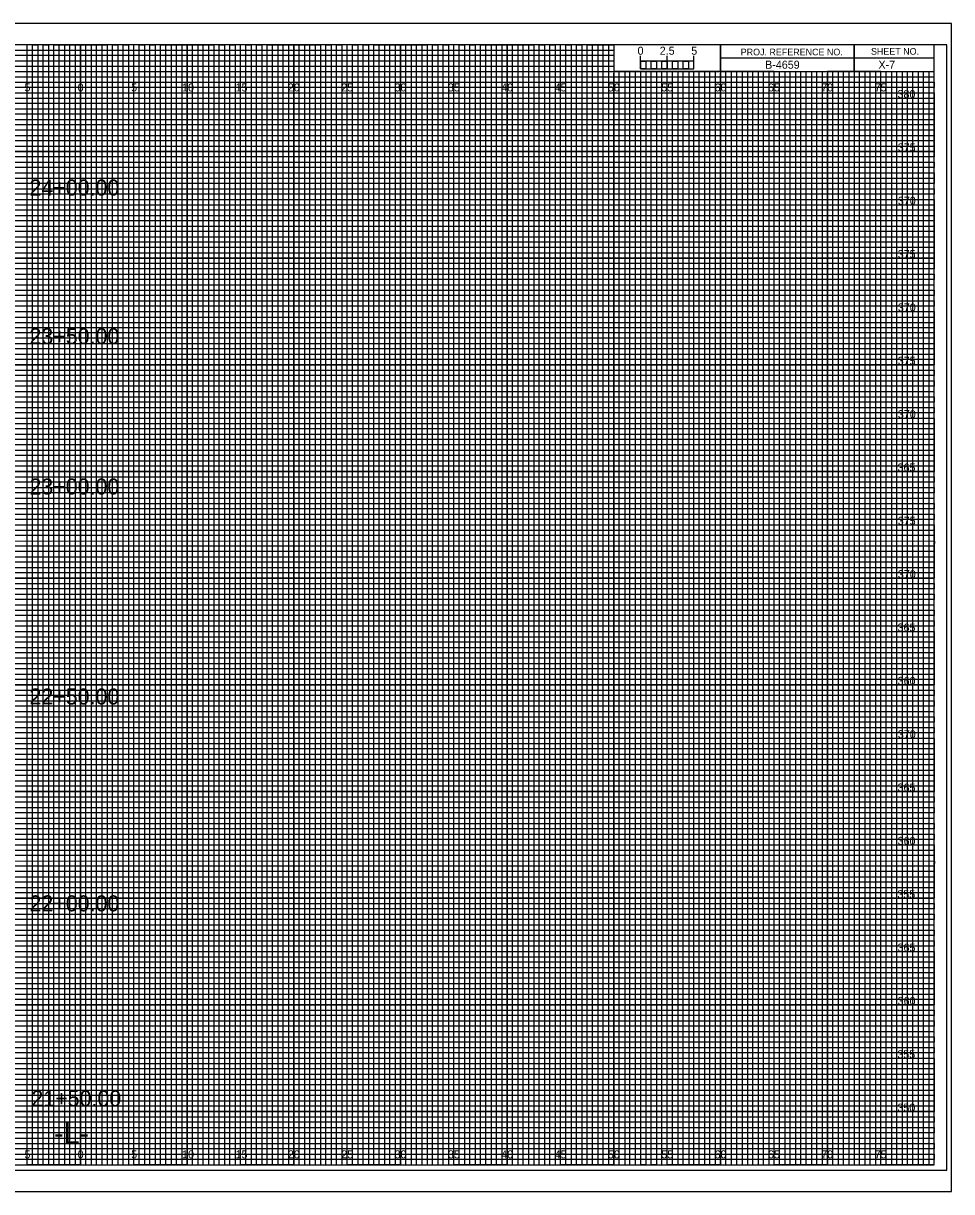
# Model space of a CAD drawing. Extents: x -7 to 162, y 658 to 767.
# Drawn here: x 74.6 to 161.7, y 657.5 to 767 of the extents above; entities that cross this region are included whole.
import ezdxf

# ---------------------------------------------------------------- set-up
doc = ezdxf.new("R2010")
doc.units = 0
for name, color, linetype in [('Prop XS Alignment Label', 7, 'Continuous'), ('Prop XS Bar Scale Labels', 7, 'Continuous'), ('Prop XS Elevation Labels', 7, 'Continuous'), ('Prop XS Offset Labels', 7, 'Continuous'), ('Prop XS Project Number', 7, 'Continuous'), ('Prop XS Sheet Number', 7, 'Continuous'), ('Prop XS Station Labels', 7, 'Continuous'), ('Sheet Cross Section CELL', 7, 'Continuous'), ('Sheet Cross Section Grid Major CELL', 7, 'Continuous'), ('Sheet Cross Section Grid Middle CELL', 7, 'Continuous'), ('Sheet Cross Section Grid Minor 1 CELL', 7, 'Continuous'), ('Sheet Cross Section Grid Minor 2 CELL', 7, 'Continuous'), ('Sheet Cross Section Scale CELL', 7, 'Continuous'), ('Sheet Cutting Line CELL', 7, 'Continuous'), ('Sheet DOT Grid CELL', 7, 'Continuous'), ('Sheet Plot Border Inside CELL', 7, 'Continuous'), ('Sheet Plot Border Outside CELL', 7, 'Continuous')]:
    doc.layers.add(name, color=color, linetype=linetype)

msp = doc.modelspace()

# ---------------------------------------------------------------- linework, layer by layer
at = {"layer": 'Sheet Cross Section CELL'}
for p, q in [((152.5, 765), (152.5, 762.5)), ((152.5, 762.5), (152.5, 765)), ((160, 763.75), (140, 763.75)), ((140, 763.75), (140, 762.5)), ((140, 762.5), (160, 762.5))]:
    msp.add_line(p, q, dxfattribs=at)
for points in [[(160, 765), (0, 765), (0, 660), (160, 660)], [(140, 765), (130, 765), (130, 762.51), (140, 762.51)], [(160, 765), (140, 765), (140, 762.5), (160, 762.5)]]:
    msp.add_lwpolyline(points, close=True, dxfattribs=at)
at = {"layer": 'Sheet Cross Section Grid Major CELL'}
for p, q in [((75, 765), (70, 765)), ((75, 660), (75, 765)), ((85, 765), (80, 765)), ((80, 765), (80, 660)), ((85, 660), (85, 765)), ((95, 765), (90, 765)), ((90, 765), (90, 660)), ((95, 660), (95, 765)), ((105, 765), (100, 765)), ((100, 765), (100, 660)), ((105, 660), (105, 765)), ((115, 765), (110, 765)), ((110, 765), (110, 660)), ((115, 660), (115, 765)), ((125, 765), (120, 765)), ((120, 765), (120, 660)), ((125, 660), (125, 765)), ((130, 765), (130, 660)), ((135, 660), (135, 762.5)), ((145, 762.5), (140, 762.5)), ((140, 762.5), (140, 660)), ((145, 660), (145, 762.5)), ((155, 762.5), (150, 762.5)), ((150, 762.5), (150, 660)), ((155, 660), (155, 762.5)), ((80, 660), (75, 660)), ((90, 660), (85, 660)), ((100, 660), (95, 660)), ((110, 660), (105, 660)), ((120, 660), (115, 660)), ((130, 660), (125, 660)), ((140, 660), (135, 660)), ((150, 660), (145, 660)), ((160, 660), (155, 660)), ((160, 660), (160, 660))]:
    msp.add_line(p, q, dxfattribs=at)
for points in [[(0, 760), (160, 760), (160, 755), (0, 755)], [(0, 750), (160, 750), (160, 745), (0, 745)], [(0, 740), (160, 740), (160, 735), (0, 735)], [(0, 730), (160, 730), (160, 725), (0, 725)], [(0, 720), (160, 720), (160, 715), (0, 715)], [(0, 710), (160, 710), (160, 705), (0, 705)], [(0, 700), (160, 700), (160, 695), (0, 695)], [(0, 690), (160, 690), (160, 685), (0, 685)], [(0, 680), (160, 680), (160, 675), (0, 675)], [(0, 670), (160, 670), (160, 665), (0, 665)]]:
    msp.add_lwpolyline(points, dxfattribs=at)
at = {"layer": 'Sheet Cross Section Grid Middle CELL'}
for points in [[(72.5, 660), (77.5, 660), (77.5, 765), (82.5, 765), (82.5, 660), (87.5, 660), (87.5, 765), (92.5, 765), (92.5, 660), (97.5, 660), (97.5, 765), (102.5, 765), (102.5, 660), (107.5, 660), (107.5, 765), (112.5, 765), (112.5, 660), (117.5, 660), (117.5, 765), (122.5, 765), (122.5, 660), (127.5, 660), (127.5, 765), (129.97, 765), (130, 765), (130, 762.5), (132.5, 762.5), (132.5, 660), (137.5, 660), (137.5, 762.5), (142.5, 762.5), (142.5, 660), (147.5, 660), (147.5, 762.5), (152.5, 762.5), (152.5, 660), (157.5, 660), (157.5, 762.5)], [(0, 762.5), (137.5, 762.5)], [(0, 752.5), (160, 752.5), (160, 757.5), (0, 757.5)], [(0, 742.5), (160, 742.5), (160, 747.5), (0, 747.5)], [(0, 732.5), (160, 732.5), (160, 737.5), (0, 737.5)], [(0, 722.5), (160, 722.5), (160, 727.5), (0, 727.5)], [(0, 712.5), (160, 712.5), (160, 717.5), (0, 717.5)], [(0, 702.5), (160, 702.5), (160, 707.5), (0, 707.5)], [(0, 692.5), (160, 692.5), (160, 697.5), (0, 697.5)], [(0, 682.5), (160, 682.5), (160, 687.5), (0, 687.5)], [(0, 672.5), (160, 672.5), (160, 677.5), (0, 677.5)], [(0, 662.5), (160, 662.5), (160, 667.5), (0, 667.5)]]:
    msp.add_lwpolyline(points, dxfattribs=at)
at = {"layer": 'Sheet Cross Section Grid Minor 1 CELL'}
for p, q in [((0, 764.5), (130, 764.5)), ((130, 764.5), (130, 763.99)), ((130, 763.99), (0, 763.99)), ((0, 763.5), (130, 763.5)), ((130, 763.5), (130, 762.95)), ((130, 762.95), (0, 762.95)), ((0, 762), (160, 762))]:
    msp.add_line(p, q, dxfattribs=at)
for points in [[(0, 761.5), (135, 761.5), (160, 761.5), (160, 761), (0, 761)], [(0, 760.5), (160, 760.5), (160, 759.5), (0, 759.5)], [(0, 759), (160, 759), (160, 758.5), (0, 758.49)], [(0, 758), (160, 758), (160, 757), (0, 757)], [(0, 756.5), (160, 756.5), (160, 756), (0, 756)], [(0, 755.5), (160, 755.5), (160, 754.5), (0, 754.5)], [(0, 754), (160, 754), (160, 753.5), (0, 753.5)], [(0, 753), (160, 753), (160, 752), (0, 752)], [(0, 751.5), (160, 751.5), (160, 751), (0, 751)], [(0, 750.5), (160, 750.5), (160, 749.5), (0, 749.5)], [(0, 749), (160, 749), (160, 748.5), (0, 748.5)], [(0, 748), (160, 748), (160, 746.98), (160, 746.5), (160, 746), (0, 746)], [(0, 747), (160, 747), (160, 746.5), (0, 746.5)], [(0, 745.5), (160, 745.5), (160, 744.5), (0, 744.51)], [(0, 744.51), (160, 744.5), (160, 744), (0, 744)], [(0, 743.5), (160, 743.5), (160, 743), (0, 743)], [(0, 742), (160, 742), (160, 741.5), (0, 741.5)], [(0, 741), (160, 741), (160, 740.5), (0, 740.5)], [(-0.04, 739.45), (160, 739.45), (160, 738.94), (-0.04, 738.94)], [(0, 738.5), (160, 738.5), (160, 738), (0, 738)], [(0, 737), (160, 737), (160, 736.5), (0, 736.5)], [(0, 736), (160, 736), (160, 735.5), (0, 735.5)], [(0, 734.5), (160, 734.5), (160, 734), (0, 734)], [(0, 733.5), (160, 733.5), (160, 733), (0, 733)], [(0, 732), (160, 732), (160, 731.5), (0, 731.5)], [(0, 731), (160, 731), (160, 730.5), (0, 730.5)], [(0, 729.5), (160, 729.5), (160, 728.99), (0, 729)], [(0, 728.5), (160, 728.5), (160, 728), (0, 728)], [(0, 727), (160, 727), (160, 726.5), (0, 726.5)], [(0, 726), (160, 726), (160, 725.5), (0, 725.5)], [(0, 724.5), (160, 724.5), (160, 724), (0, 724)], [(0, 723.5), (160, 723.5), (160, 723), (0, 723)], [(0, 722), (160, 722), (160, 721.5), (0, 721.5)], [(0, 721), (160, 721), (160, 720.5), (0, 720.5)], [(0, 719.5), (160, 719.5), (160, 719), (0, 719)], [(0, 718.5), (160.03, 718.46), (160, 718), (0, 718)], [(0, 717), (160, 717), (160, 716.5), (0, 716.5)], [(0, 716), (160, 716), (160, 715.5), (0, 715.5)], [(0, 714.5), (160, 714.5), (160, 714), (0, 714)], [(0, 713.5), (160, 713.5), (160, 713), (0, 713)], [(0, 712), (160, 712), (160, 711.5), (0, 711.5)], [(0, 711), (160, 711), (160, 710.5), (0, 710.5)], [(0, 709.5), (160, 709.5), (160, 709), (0, 709)], [(0, 708.5), (160, 708.5), (160, 708), (0, 708)], [(0, 707), (160, 707), (160, 706.5), (0, 706.5)], [(0, 706), (160, 706), (160, 705.5), (0, 705.5)], [(0, 704.5), (160, 704.5), (160, 704), (0, 704)], [(0, 703.5), (160, 703.5), (160, 703), (0, 703)], [(0, 702), (160, 702), (160, 701.5), (0, 701.5)], [(0, 701), (160, 701), (160, 700.5), (0, 700.5)], [(0, 699.5), (160, 699.5), (160, 698.99), (0, 699)], [(0, 698.5), (160, 698.5), (160, 698), (0, 698)], [(0, 697), (160, 697), (160, 696.5), (0, 696.5)], [(0, 696), (160, 696), (160, 695.5), (0, 695.5)], [(0, 694.5), (160, 694.5), (160, 694), (0, 694)], [(0, 693.5), (160, 693.5), (160, 693), (0, 693)], [(0, 692), (160, 692), (160, 691.5), (0, 691.5)], [(0, 691), (160, 691), (160, 690.5), (0, 690.5)], [(0, 689.5), (160, 689.5), (160, 689), (0, 689)], [(0, 688.5), (160.03, 688.46), (160, 688), (0, 688)], [(0, 687), (160, 687), (160, 686.5), (0, 686.5)], [(0, 686), (160, 686), (160, 685.5), (0, 685.5)], [(0, 684.5), (160, 684.5), (160, 684), (0, 684)], [(0, 683.5), (160, 683.5), (160, 683), (0, 683)], [(0, 682), (160, 682), (160, 681.5), (0, 681.5)], [(0, 681), (160, 681), (160, 680.5), (0, 680.5)], [(0, 679.5), (160, 679.5), (160, 679), (0, 679)], [(0, 678.5), (160, 678.5), (160, 678), (0, 678)], [(0, 677), (160, 677), (160, 676.5), (0, 676.5)], [(0, 676), (160, 676), (160, 675.5), (0, 675.5)], [(0, 674.5), (160, 674.5), (160, 674), (0, 674)], [(0, 673.5), (160, 673.5), (160, 673), (0, 673)], [(0, 672), (160, 672), (160, 671.5), (0, 671.5)], [(0, 671), (160, 671), (160, 670.5), (0, 670.5)], [(0, 669.5), (160, 669.5), (160, 669), (0, 669)], [(0, 668.5), (160, 668.5), (160, 668), (0, 668)], [(0, 667), (160, 667), (160, 666.5), (0, 666.5)], [(0, 666), (160, 666), (160, 665.5), (0, 665.5)], [(0, 664.5), (160, 664.5), (160, 664), (0, 664)], [(0, 663.5), (160, 663.5), (160, 663), (0, 663)], [(0, 662), (160, 662), (160, 661.5), (0, 661.5)], [(0, 661), (160, 661), (160, 660.5), (0, 660.5)]]:
    msp.add_lwpolyline(points, dxfattribs=at)
at = {"layer": 'Sheet Cross Section Grid Minor 2 CELL'}
for p, q in [((133.5, 762.5), (133, 762.5)), ((133, 762.5), (133, 660)), ((133.5, 660), (133.5, 762.5)), ((134.5, 762.5), (134, 762.5)), ((134, 762.5), (134, 660)), ((134.5, 660), (134.5, 762.5)), ((133, 660), (132.5, 660)), ((134, 660), (133.5, 660))]:
    msp.add_line(p, q, dxfattribs=at)
for points in [[(75, 660), (75.5, 660), (75.5, 765), (76, 765), (76, 660)], [(76, 660), (76.5, 660), (76.5, 765), (77, 765), (77, 660)], [(77.5, 660), (78, 660), (78, 765), (78.5, 765), (78.5, 660)], [(78.5, 660), (79, 660), (79, 765), (79.5, 765), (79.5, 660)], [(80, 660), (80.5, 660), (80.5, 765), (81, 765), (81, 660)], [(81, 660), (81.5, 660), (81.5, 765), (82, 765), (82, 660)], [(82.5, 660), (83, 660), (83, 765), (83.5, 765), (83.5, 660)], [(83.5, 660), (84, 660), (84, 765), (84.5, 765), (84.5, 660)], [(85, 660), (85.5, 660), (85.5, 765), (86, 765), (86, 660)], [(86, 660), (86.5, 660), (86.5, 765), (87, 765), (87, 660)], [(87.5, 660), (88, 660), (88, 765), (88.5, 765), (88.5, 660)], [(88.5, 660), (89, 660), (89, 765), (89.5, 765), (89.5, 660)], [(90, 660), (90.5, 660), (90.5, 765), (91, 765), (91, 660)], [(91, 660), (91.5, 660), (91.5, 765), (92, 765), (92, 660)], [(92.5, 660), (93, 660), (93, 765), (93.5, 765), (93.5, 660)], [(93.5, 660), (94, 660), (94, 765), (94.5, 765), (94.5, 660)], [(95, 660), (95.5, 660), (95.5, 765), (96, 765), (96, 660)], [(96, 660), (96.5, 660), (96.5, 765), (97, 765), (97, 660)], [(97.5, 660), (98, 660), (98, 765), (98.5, 765), (98.5, 660)], [(98.5, 660), (99, 660), (99, 765), (99.5, 765), (99.5, 660)], [(100, 660), (100.5, 660), (100.5, 765), (101, 765), (101, 660)], [(101, 660), (101.5, 660), (101.5, 765), (102, 765), (102, 660)], [(102.5, 660), (103, 660), (103, 765), (103.5, 765), (103.5, 660)], [(103.5, 660), (104, 660), (104, 765), (104.5, 765), (104.5, 660)], [(105, 660), (105.5, 660), (105.5, 765), (106, 765), (106, 660)], [(106, 660), (106.5, 660), (106.5, 765), (107, 765), (107, 660)], [(107.5, 660), (108, 660), (108, 765), (108.5, 765), (108.5, 660)], [(108.5, 660), (109, 660), (109, 765), (109.5, 765), (109.5, 660)], [(110, 660), (110.5, 660), (110.5, 765), (111, 765), (111, 660)], [(111, 660), (111.5, 660), (111.5, 765), (112, 765), (112, 660)], [(112.5, 660), (113, 660), (113, 765), (113.5, 765), (113.5, 660)], [(113.5, 660), (114, 660), (114, 765), (114.5, 765), (114.5, 660)], [(115, 660), (115.5, 660), (115.5, 765), (116, 765), (116, 660)], [(116, 660), (116.5, 660), (116.5, 765), (117, 765), (117, 660)], [(117.5, 660), (118, 660), (118, 765), (118.5, 765), (118.5, 660)], [(118.5, 660), (119, 660), (119, 765), (119.5, 765), (119.5, 660)], [(120, 660), (120.5, 660), (120.5, 765), (121, 765), (121, 660)], [(121, 660), (121.5, 660), (121.5, 765), (122, 765), (122, 660)], [(122.5, 660), (123, 660), (123, 765), (123.5, 765), (123.5, 660)], [(123.5, 660), (124, 660), (124, 765), (124.5, 765), (124.5, 660)], [(125, 660), (125.5, 660), (125.5, 765), (126, 765), (126, 660)], [(126, 660), (126.5, 660), (126.5, 765), (127, 765), (127, 660)], [(127.5, 660), (128, 660), (128, 765), (128.5, 765), (128.5, 660)], [(128.5, 660), (129, 660), (129, 765), (129.5, 765), (129.5, 660)], [(130, 660), (130.5, 660), (130.5, 762.5), (131.01, 762.5), (131.01, 660)], [(131, 660), (131.5, 660), (131.5, 762.5), (132, 762.5), (132, 660)], [(135, 660), (135.49, 660), (135.49, 762.5), (136, 762.5), (136, 660)], [(136, 660), (136.5, 660), (136.5, 762.5), (137.03, 762.5), (137.03, 660)], [(137.5, 660), (138, 660), (138, 762.5), (138.5, 762.5), (138.5, 660)], [(138.5, 660), (139, 660), (139, 762.5), (139.5, 762.5), (139.5, 660)], [(140, 660), (140.5, 660), (140.5, 762.5), (141, 762.5), (141, 660)], [(141, 660), (141.5, 660), (141.5, 762.5), (142, 762.5), (142, 660)], [(142.5, 660), (143, 660), (143, 762.5), (143.5, 762.5), (143.5, 660)], [(143.5, 660), (144, 660), (144, 762.5), (144.5, 762.5), (144.5, 660)], [(145, 660), (145.5, 660), (145.5, 762.5), (146, 762.5), (146, 660)], [(146, 660), (146.5, 660), (146.5, 762.5), (147, 762.5), (147, 660)], [(147.5, 660), (148, 660), (148, 762.5), (148.5, 762.5), (148.5, 660)], [(148.5, 660), (149, 660), (149, 762.5), (149.5, 762.5), (149.5, 660)], [(150, 660), (150.5, 660), (150.5, 762.5), (151, 762.5), (151, 660)], [(151, 660), (151.5, 660), (151.5, 762.5), (152, 762.5), (152, 660)], [(152.5, 660), (153, 660), (153, 762.5), (153.5, 762.5), (153.5, 660)], [(153.5, 660), (154, 660), (154, 762.5), (154.5, 762.5), (154.5, 660)], [(155, 660), (155.5, 660), (155.5, 762.5), (156, 762.5), (156, 660)], [(156, 660), (156.5, 660), (156.5, 762.5), (157, 762.5), (157, 660)], [(157.5, 660), (158, 660), (158, 762.5), (158.5, 762.5), (158.5, 660)], [(158.5, 660), (159, 660), (159, 762.5), (159.5, 762.5), (159.5, 660)]]:
    msp.add_lwpolyline(points, dxfattribs=at)
at = {"layer": 'Sheet Cross Section Scale CELL'}
for p, q in [((132.5, 762.75), (132.5, 763.95)), ((132.5, 763.45), (132.5, 763.95)), ((135, 762.75), (135, 763.95)), ((137.5, 762.75), (137.5, 763.95)), ((137.5, 763.45), (137.5, 763.95))]:
    msp.add_line(p, q, dxfattribs=at)
for points in [[(137.5, 763.45), (132.5, 763.45), (132.5, 762.75), (137.5, 762.75)], [(132.5, 763.45), (133, 763.45), (133, 762.75), (132.5, 762.75)], [(133.5, 763.45), (134, 763.45), (134, 762.75), (133.5, 762.75)], [(134.5, 763.45), (135, 763.45), (135, 762.75), (134.5, 762.75)], [(135.5, 763.45), (136, 763.45), (136, 762.75), (135.5, 762.75)], [(136.5, 763.45), (137, 763.45), (137, 762.75), (136.5, 762.75)]]:
    msp.add_lwpolyline(points, close=True, dxfattribs=at)
at = {"layer": 'Sheet Cutting Line CELL'}
for p, q in [((161.65, 767), (-6.7, 767)), ((-6.7, 657.5), (161.65, 657.5))]:
    msp.add_line(p, q, dxfattribs=at)
at = {"layer": 'Sheet DOT Grid CELL'}
for p, q in [((75, 660), (75, 765)), ((80, 660), (80, 765)), ((85, 660), (85, 765)), ((90, 660), (90, 765)), ((95, 660), (95, 765)), ((100, 660), (100, 765)), ((105, 660), (105, 765)), ((110, 660), (110, 765)), ((115, 660), (115, 765)), ((120, 660), (120, 765)), ((125, 660), (125, 765)), ((130, 660), (130, 762.34)), ((135, 660), (135, 762.34)), ((140, 660), (140, 762.34)), ((145, 660), (145, 762.34)), ((150, 660), (150, 762.34)), ((155, 660), (155, 762.34)), ((0, 760), (160, 760)), ((0, 755), (160, 755)), ((0, 750), (160, 750)), ((0, 745), (160, 745)), ((0, 740), (160, 740)), ((0, 735), (160, 735)), ((0, 730), (160, 730)), ((0, 725), (160, 725)), ((0, 720), (160, 720)), ((0, 715), (160, 715)), ((0, 710), (160, 710)), ((0, 705), (160, 705)), ((0, 700), (160, 700)), ((0, 695), (160, 695)), ((0, 690), (160, 690)), ((0, 685), (160, 685)), ((0, 680), (160, 680)), ((0, 675), (160, 675)), ((0, 670), (160, 670)), ((0, 665), (160, 665))]:
    msp.add_line(p, q, dxfattribs=at)
at = {"layer": 'Sheet Plot Border Inside CELL'}
msp.add_lwpolyline([(-5.4, 659.5), (161.2, 659.5), (161.2, 765), (-5.4, 765)], close=True, dxfattribs=at)
at = {"layer": 'Sheet Plot Border Outside CELL'}
msp.add_lwpolyline([(-6.7, 657.5), (161.65, 657.5), (161.65, 767), (-6.7, 767)], close=True, dxfattribs=at)

# ---------------------------------------------------------------- texts
at = {"layer": 'Prop XS Alignment Label'}
msp.add_text('-L-', height=2, dxfattribs=at).set_placement((77.53, 662))
at = {"layer": 'Prop XS Bar Scale Labels'}
for s, p in [('2.5', (134.29, 764.06)), ('5', (137.24, 764.06))]:
    msp.add_text(s, height=0.75, dxfattribs=at).set_placement(p)
at = {"layer": 'Prop XS Elevation Labels'}
for s, p in [('380', (156.58, 760)), ('375', (156.6, 755)), ('370', (156.61, 750)), ('375', (156.6, 745)), ('370', (156.61, 740)), ('375', (156.6, 735)), ('370', (156.61, 730)), ('365', (156.58, 725)), ('375', (156.6, 720)), ('370', (156.61, 715)), ('365', (156.58, 710)), ('360', (156.59, 705)), ('370', (156.61, 700)), ('365', (156.58, 695)), ('360', (156.59, 690)), ('355', (156.56, 685)), ('365', (156.58, 680)), ('360', (156.59, 675)), ('355', (156.56, 670)), ('350', (156.57, 665))]:
    msp.add_text(s, height=0.75, dxfattribs=at).set_placement(p)
at = {"layer": 'Prop XS Offset Labels'}
for s, p in [('5', (74.74, 760.62)), ('0', (79.73, 760.62)), ('0', (79.73, 760.62)), ('5', (84.74, 760.62)), ('10', (89.52, 760.62)), ('15', (94.53, 760.62)), ('20', (99.43, 760.62)), ('25', (104.44, 760.62)), ('30', (109.43, 760.62)), ('35', (114.44, 760.62)), ('40', (119.43, 760.62)), ('45', (124.44, 760.62)), ('50', (129.43, 760.62)), ('55', (134.44, 760.62)), ('60', (139.43, 760.62)), ('65', (144.44, 760.62)), ('70', (149.43, 760.62)), ('75', (154.44, 760.62)), ('0', (79.73, 660.62)), ('0', (79.73, 660.62)), ('10', (89.52, 660.62)), ('20', (99.43, 660.62)), ('25', (104.44, 660.62)), ('30', (109.43, 660.62)), ('35', (114.44, 660.62)), ('40', (119.43, 660.62)), ('50', (129.43, 660.62)), ('60', (139.43, 660.62)), ('65', (144.44, 660.62)), ('70', (149.43, 660.62)), ('5', (74.74, 660.62)), ('5', (84.74, 660.62)), ('15', (94.53, 660.62)), ('45', (124.44, 660.62)), ('55', (134.44, 660.62)), ('75', (154.44, 660.62))]:
    msp.add_text(s, height=0.75, dxfattribs=at).set_placement(p)
at = {"layer": 'Prop XS Project Number'}
msp.add_text('B-4659', height=0.75, dxfattribs=at).set_placement((144.17, 762.75))
at = {"layer": 'Prop XS Sheet Number'}
msp.add_text('X-7', height=0.75, dxfattribs=at).set_placement((154.79, 762.75))
at = {"layer": 'Prop XS Station Labels'}
for s, p in [('24+00.00', (75.21, 750.86)), ('23+50.00', (75.21, 736.93)), ('23+00.00', (75.21, 722.84)), ('22+50.00', (75.21, 703.16)), ('22+00.00', (75.21, 683.77)), ('21+50.00', (75.39, 665.49))]:
    msp.add_text(s, height=1.5, dxfattribs=at).set_placement(p)
at = {"layer": 'Sheet Cross Section CELL'}
for s, p in [('PROJ. REFERENCE NO.', (141.88, 764)), ('SHEET NO.', (154.09, 764.06))]:
    msp.add_text(s, height=0.625, dxfattribs=at).set_placement(p)
at = {"layer": 'Sheet Cross Section Scale CELL'}
msp.add_text('0', height=0.75, dxfattribs=at).set_placement((132.21, 764.06))

doc.saveas('drawing.dxf')
